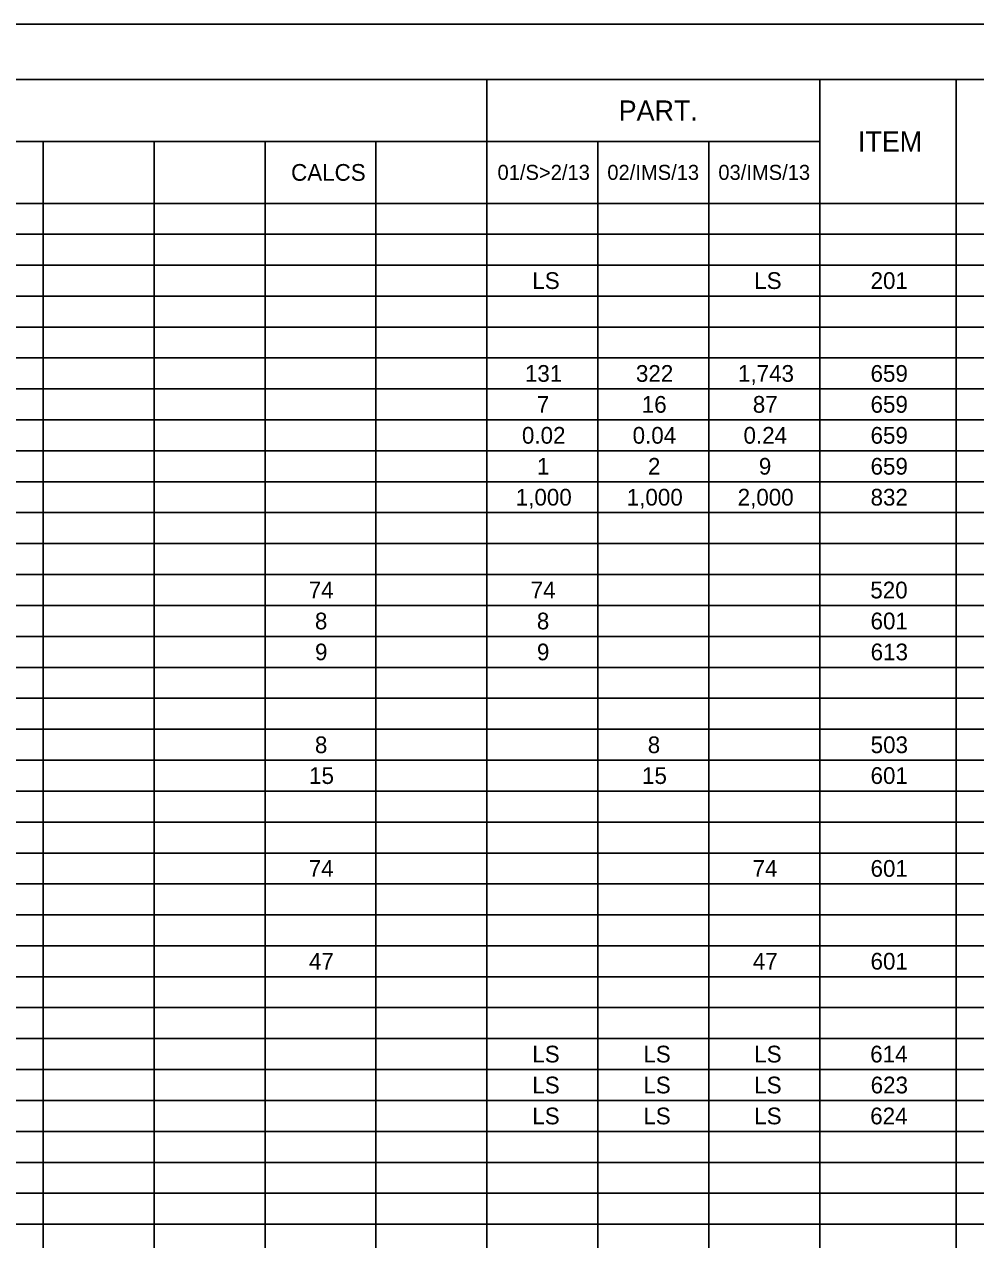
# Model space of a CAD drawing. Extents: x 0 to 34, y 0 to 22.
# Drawn here: x 8.36 to 16.97, y 11 to 22 of the extents above; entities that cross this region are included whole.
import ezdxf

# ---------------------------------------------------------------- set-up
doc = ezdxf.new("R2010")
doc.units = 0
for name, color, linetype in [('Default', 7, 'Continuous'), ('SH_Border', 7, 'Continuous'), ('SH_Cut_Line', 7, 'Continuous')]:
    doc.layers.add(name, color=color, linetype=linetype)

msp = doc.modelspace()

# ---------------------------------------------------------------- linework, layer by layer
at = {"layer": 'Default'}
for p, q in [((1.5, 21.5), (31.997, 21.5)), ((12.55, 21.5), (12.55, 0.504)), ((15.563, 21.5), (15.563, 0.504)), ((16.798, 21.5), (16.798, 0.504)), ((1.5, 20.94), (15.563, 20.94)), ((8.532, 20.94), (8.532, 0.504)), ((9.536, 20.94), (9.536, 0.504)), ((10.541, 20.94), (10.541, 0.504)), ((11.545, 20.94), (11.545, 0.504)), ((13.554, 20.94), (13.554, 0.504)), ((14.559, 20.94), (14.559, 0.504)), ((1.5, 20.38), (31.997, 20.38)), ((1.5, 20.1), (31.997, 20.1)), ((1.5, 19.82), (31.997, 19.82)), ((1.5, 19.54), (31.997, 19.54)), ((1.5, 19.26), (31.997, 19.26)), ((1.5, 18.981), (31.997, 18.981)), ((1.5, 18.701), (31.997, 18.701)), ((1.5, 18.421), (31.997, 18.421)), ((1.5, 18.141), (31.997, 18.141)), ((1.5, 17.861), (31.997, 17.861)), ((1.5, 17.581), (31.997, 17.581)), ((1.5, 17.301), (31.997, 17.301)), ((1.5, 17.021), (31.997, 17.021)), ((1.5, 16.741), (31.997, 16.741)), ((1.5, 16.461), (31.997, 16.461)), ((1.5, 16.181), (31.997, 16.181)), ((1.5, 15.901), (31.997, 15.901)), ((1.5, 15.621), (31.997, 15.621)), ((1.5, 15.341), (31.997, 15.341)), ((1.5, 15.061), (31.997, 15.061)), ((1.5, 14.781), (31.997, 14.781)), ((1.5, 14.501), (31.997, 14.501)), ((1.5, 14.221), (31.997, 14.221)), ((1.5, 13.942), (31.997, 13.942)), ((1.5, 13.662), (31.997, 13.662)), ((1.5, 13.382), (31.997, 13.382)), ((1.5, 13.102), (31.997, 13.102)), ((1.5, 12.822), (31.997, 12.822)), ((1.5, 12.542), (31.997, 12.542)), ((1.5, 12.262), (31.997, 12.262)), ((1.5, 11.982), (31.997, 11.982)), ((1.5, 11.702), (31.997, 11.702)), ((1.5, 11.422), (31.997, 11.422)), ((1.5, 11.142), (31.997, 11.142))]:
    msp.add_line(p, q, dxfattribs=at)
at = {"layer": 'SH_Border'}
msp.add_lwpolyline([(1.5, 21.5), (33.5, 21.5), (33.5, 0.5), (1.5, 0.5)], close=True, dxfattribs=at)
at = {"layer": 'SH_Cut_Line'}
msp.add_lwpolyline([(0, 0), (34, 0), (34, 22), (0, 22)], close=True, dxfattribs=at)

# ---------------------------------------------------------------- texts
at = {"layer": 'Default'}
for s, height, p in [('PART.', 0.1818, (13.743, 21.129)), ('ITEM', 0.1818, (15.909, 20.849)), ('CALCS', 0.1515, (10.777, 20.584)), ('01/S>2/13', 0.1363, (12.646, 20.592)), ('02/IMS/13', 0.1363, (13.64, 20.592)), ('03/IMS/13', 0.1363, (14.645, 20.592)), ('LS', 0.1515, (12.961, 19.605)), ('LS', 0.1515, (14.97, 19.605)), ('201', 0.1515, (16.023, 19.605)), ('131', 0.1515, (12.894, 18.765)), ('322', 0.1515, (13.899, 18.765)), ('1,743', 0.1515, (14.823, 18.765)), ('659', 0.1515, (16.023, 18.765)), ('7', 0.151, (13.002, 18.485)), ('16', 0.1515, (13.952, 18.485)), ('87', 0.1515, (14.957, 18.485)), ('659', 0.1515, (16.023, 18.485)), ('0.02', 0.1515, (12.867, 18.205)), ('0.04', 0.1515, (13.869, 18.205)), ('0.24', 0.1515, (14.873, 18.205)), ('659', 0.1515, (16.023, 18.205)), ('1', 0.151, (13.003, 17.925)), ('2', 0.151, (14.008, 17.925)), ('9', 0.151, (15.012, 17.925)), ('659', 0.1515, (16.023, 17.925)), ('1,000', 0.1515, (12.811, 17.645)), ('1,000', 0.1515, (13.816, 17.645)), ('2,000', 0.1515, (14.82, 17.645)), ('832', 0.1515, (16.023, 17.645)), ('74', 0.1515, (10.937, 16.805)), ('74', 0.1515, (12.946, 16.805)), ('520', 0.1515, (16.021, 16.805)), ('8', 0.151, (10.993, 16.525)), ('8', 0.151, (13.002, 16.525)), ('601', 0.1515, (16.023, 16.525)), ('9', 0.151, (10.994, 16.245)), ('9', 0.151, (13.003, 16.245)), ('613', 0.1515, (16.024, 16.245)), ('8', 0.151, (10.993, 15.405)), ('8', 0.151, (14.006, 15.405)), ('503', 0.1515, (16.024, 15.405)), ('15', 0.1515, (10.94, 15.126)), ('15', 0.1515, (13.954, 15.126)), ('601', 0.1515, (16.023, 15.126)), ('74', 0.1515, (10.937, 14.286)), ('74', 0.1515, (14.955, 14.286)), ('601', 0.1515, (16.023, 14.286)), ('47', 0.1515, (10.939, 13.446)), ('47', 0.1515, (14.957, 13.446)), ('601', 0.1515, (16.023, 13.446)), ('LS', 0.1515, (12.961, 12.606)), ('LS', 0.1515, (13.966, 12.606)), ('LS', 0.1515, (14.97, 12.606)), ('614', 0.1515, (16.02, 12.606)), ('LS', 0.1515, (12.961, 12.326)), ('LS', 0.1515, (13.966, 12.326)), ('LS', 0.1515, (14.97, 12.326)), ('623', 0.1515, (16.024, 12.326)), ('LS', 0.1515, (12.961, 12.046)), ('LS', 0.1515, (13.966, 12.046)), ('LS', 0.1515, (14.97, 12.046)), ('624', 0.1515, (16.02, 12.046))]:
    msp.add_text(s, height=height, dxfattribs=at).set_placement(p)

doc.saveas('drawing.dxf')
